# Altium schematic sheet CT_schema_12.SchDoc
size 277 x 170 mm
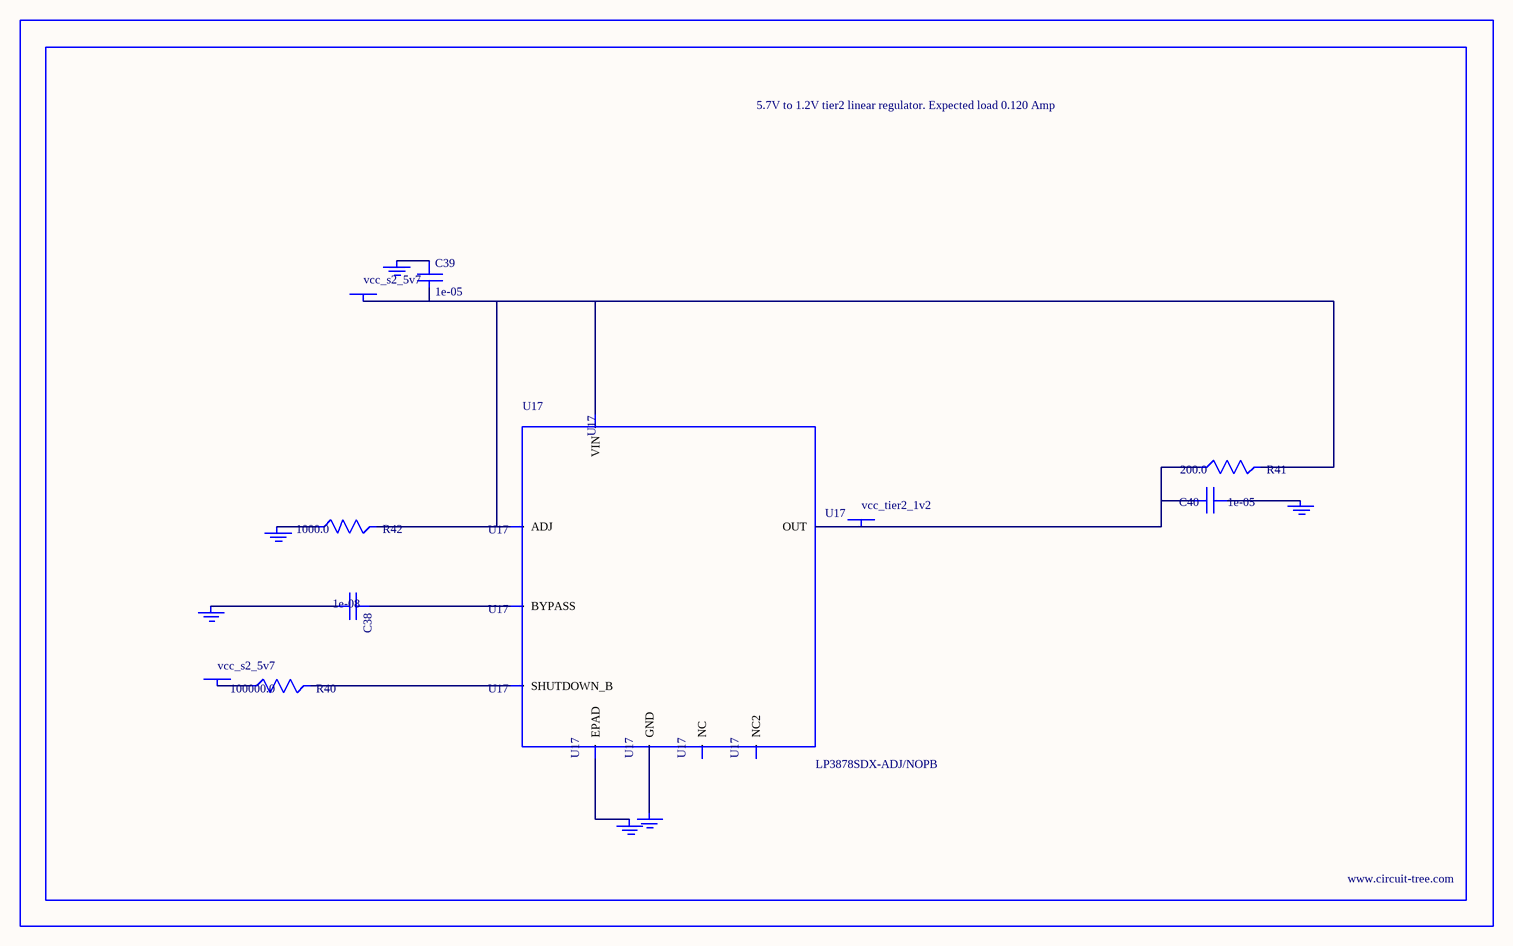
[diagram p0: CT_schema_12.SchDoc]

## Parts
BORDER11  (no value)
C38  1e-08  [C0402]
C39  1e-05  [C1206]
C40  1e-05  [C0805]
GND_INSTANCE_11_0  (no value)
GND_INSTANCE_11_1  (no value)
GND_INSTANCE_11_2  (no value)
GND_INSTANCE_11_3  (no value)
GND_INSTANCE_11_4  (no value)
GND_INSTANCE_11_5  (no value)
POWER_INSTANCE_11_0  vcc_s2_5v7
POWER_INSTANCE_11_1  vcc_s2_5v7
POWER_INSTANCE_11_2  vcc_tier2_1v2
R40  100000.0  [R0603]
R41  200.0  [R0603]
R42  1000.0  [R0603]
U17  LP3878SDX-ADJ/NOPB  [WSON-8]

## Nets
NetC38_1: C38.1 U17.1(BYPASS)
NetC38_2: C38.2 GND_INSTANCE_11_0.0(GND)
NetC39_1: C39.1 GND_INSTANCE_11_1.0(GND)
NetC39_2: C39.2 POWER_INSTANCE_11_0.0(PWR) R41.2 R42.2 U17.4(VIN) U17.6(ADJ)
NetC40_1: C40.1 GND_INSTANCE_11_2.0(GND)
NetC40_2: C40.2 POWER_INSTANCE_11_2.0(PWR) R41.1 U17.5(OUT)
NetGND_INSTANCE_11_3_0: GND_INSTANCE_11_3.0(GND) R42.1
NetGND_INSTANCE_11_4_0: GND_INSTANCE_11_4.0(GND) U17.PAD(EPAD)
NetGND_INSTANCE_11_5_0: GND_INSTANCE_11_5.0(GND) U17.3(GND)
NetPOWER_INSTANCE_11_1_0: POWER_INSTANCE_11_1.0(PWR) R40.1
NetR40_2: R40.2 U17.8(SHUTDOWN_B)

Not connected (* = marked no-connect by the designer): U17 2(NC) 7(NC2)

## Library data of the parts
BORDER11 = BORDER_PAGE11
C38 = C0402C103K3RAC
C39 = C1206C106K3RACTU
C40 = GRM219R60J106ME19D
GND_INSTANCE_11_0-GND_INSTANCE_11_5 = GND
POWER_INSTANCE_11_0-POWER_INSTANCE_11_2 = PWR
R40 = RC0603JR-07100KL
R41 = RC0603JR-07200RL
R42 = RC0603JR-071KL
